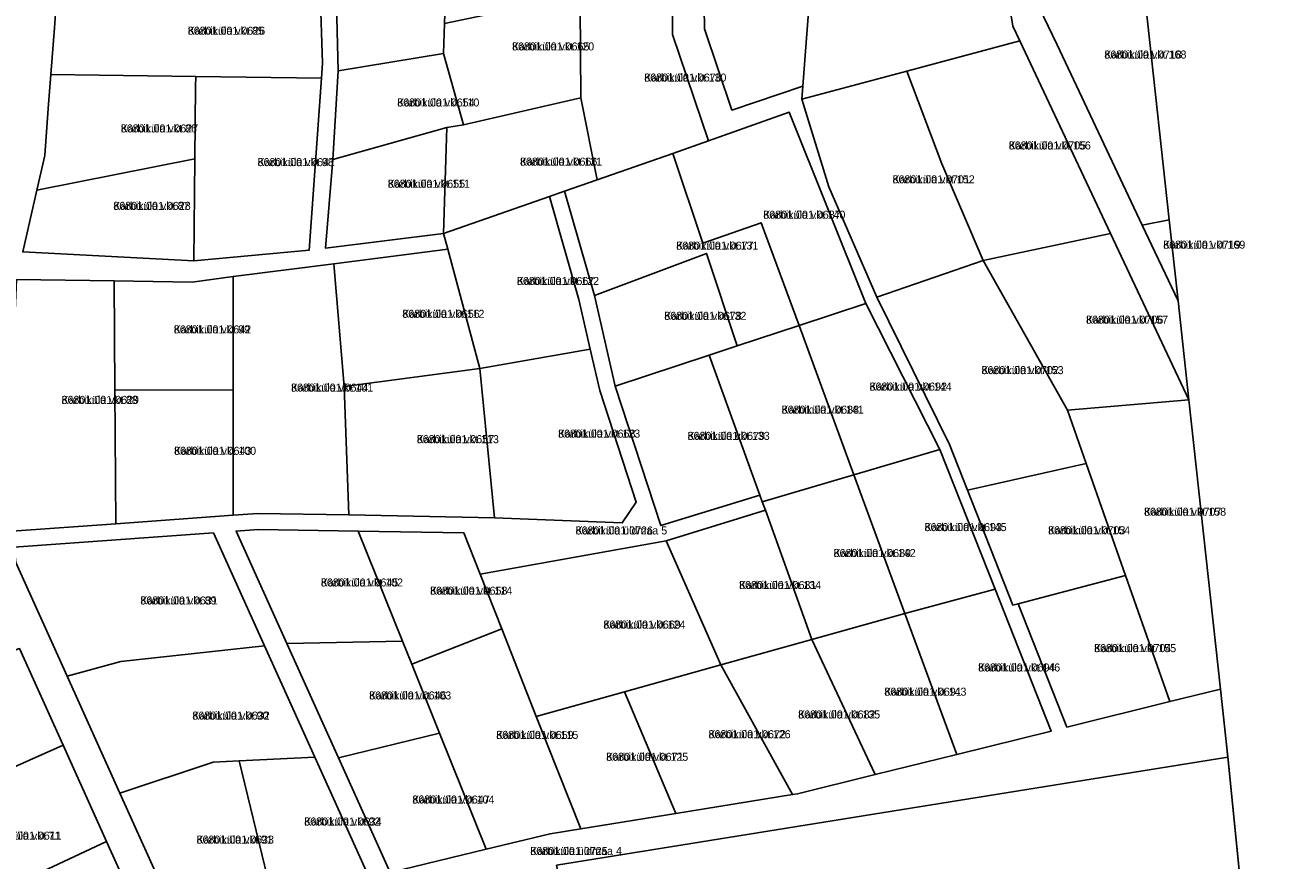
# Model space of a CAD drawing. Extents: x 484607 to 525396, y 6554521 to 6586559.
# Drawn here: x 517147.5 to 517380.7, y 6565288.3 to 6565444.8 of the extents above; entities that cross this region are included whole.
import ezdxf

# ---------------------------------------------------------------- set-up
doc = ezdxf.new("R2010")
doc.units = 0
for name, color, linetype in [('L_AADRESS', 7, 'Continuous'), ('PIIR', 7, 'Continuous'), ('TUNNUS', 7, 'Continuous')]:
    doc.layers.add(name, color=color, linetype=linetype)

msp = doc.modelspace()

# ---------------------------------------------------------------- linework, layer by layer
at = {"layer": 'PIIR'}
for points in [[(517389.61, 6565141.22), (517372.92, 6565307.66), (517371.53, 6565320.36), (517365.62, 6565374.54), (517363.6, 6565393.06), (517361.94, 6565408.22), (517357.88, 6565445.46), (517356.75, 6565455.84), (517355.62, 6565466.19), (517354.54, 6565476.06), (517353.45, 6565486.02), (517352, 6565499.3), (517350.78, 6565510.46), (517349.66, 6565520.75), (517348.53, 6565531.14), (517347.53, 6565540.29), (517346.37, 6565550.88), (517344.46, 6565568.44), (517344.15, 6565574.52), (517326.68, 6565708.93), (517381.83, 6565717.8)], [(517274.53, 6565464.55), (517274.86, 6565444.02), (517279.99, 6565428.81), (517293.29, 6565433.3), (517293.11, 6565430.86), (517298.16, 6565414.43), (517307.13, 6565393.74), (517320.76, 6565366.14), (517324.15, 6565357.6), (517332.65, 6565336.1), (517333.63, 6565336.35), (517342.77, 6565313.23), (517362.06, 6565318.01), (517371.53, 6565320.36), (517372.92, 6565307.64), (517247.1, 6565287.39)], [(517205.84, 6565451.13), (517206.19, 6565436.13), (517205.22, 6565419.54), (517203.82, 6565402.97), (517225.97, 6565405.68), (517226.76, 6565402.76), (517205.39, 6565400.01), (517186.54, 6565397.62), (517178.85, 6565396.59), (517164.22, 6565396.83), (517145.95, 6565397.1)], [(517153.32, 6565447.7), (517153.05, 6565444.2), (517152.38, 6565435.44), (517151.9, 6565429.1), (517151.24, 6565420.32), (517149.75, 6565413.79), (517147.12, 6565402.24), (517179.16, 6565400.54), (517200.79, 6565402.57), (517203.07, 6565434.8), (517203.27, 6565437.6), (517202.84, 6565451.04)], [(517338.41, 6565446.35), (517340.94, 6565441.01), (517356.89, 6565407.25), (517363.6, 6565393.06), (517365.62, 6565374.54), (517350.95, 6565405.67), (517333.93, 6565441.79), (517332.63, 6565444.55), (517331.62, 6565450.69)], [(517215.98, 6565286.02), (517233.94, 6565290.37), (517245.91, 6565293.28), (517251.66, 6565294.2), (517269.51, 6565297.07), (517291.35, 6565300.59), (517292.26, 6565300.74), (517306.86, 6565304.35), (517322.13, 6565308.13), (517339.83, 6565312.51), (517329.31, 6565339.05), (517318.98, 6565365.23), (517305.06, 6565392.61), (517290.7, 6565428.43), (517275.6, 6565423.05), (517268.87, 6565442.98), (517268.77, 6565450.06)], [(517145.13, 6565349.92), (517164.54, 6565351.33), (517186.51, 6565352.93), (517191.15, 6565353.26), (517208.24, 6565352.99), (517235.52, 6565352.42), (517259.44, 6565351.47), (517262.06, 6565355.37), (517255.23, 6565376.29), (517253.45, 6565384.04), (517251.32, 6565393.3), (517245.82, 6565412.6), (517248.65, 6565413.59), (517254.22, 6565394.05), (517258.13, 6565377.09), (517266.69, 6565350.97), (517285.24, 6565356.69), (517285.69, 6565355.43), (517286.26, 6565353.87), (517267.69, 6565348.14), (517232.82, 6565341.87), (517229.74, 6565349.65), (517209.99, 6565349.96), (517191.23, 6565350.26), (517187.1, 6565349.96), (517196.61, 6565328.9), (517206.27, 6565307.51), (517215.98, 6565286.02)], [(517212.02, 6565285.06), (517201.84, 6565307.61), (517192.42, 6565328.46), (517182.85, 6565349.65), (517145.48, 6565346.94)], [(517145.81, 6565344.07), (517155.44, 6565322.76), (517165.33, 6565300.84), (517176.36, 6565276.42)], [(517170.74, 6565274.29), (517162.82, 6565291.83), (517154.68, 6565309.84), (517146.51, 6565327.95)]]:
    msp.add_lwpolyline(points, dxfattribs=at)
for points in [[(517274.53, 6565464.55), (517295.86, 6565467.39), (517295.33, 6565460.32), (517293.29, 6565433.3), (517279.99, 6565428.81), (517274.86, 6565444.02)], [(517295.33, 6565460.32), (517331.7, 6565466.78), (517331.62, 6565450.69), (517332.63, 6565444.55), (517333.93, 6565441.79), (517312.77, 6565436.12), (517293.11, 6565430.86), (517293.29, 6565433.3)], [(517337.63, 6565452.48), (517356.75, 6565455.84), (517357.88, 6565445.46), (517361.94, 6565408.22), (517356.89, 6565407.25), (517340.94, 6565441.01), (517338.41, 6565446.35), (517337.62, 6565451.16)], [(517205.84, 6565451.13), (517226.44, 6565453.98), (517226.14, 6565445.02), (517225.96, 6565439.42), (517206.19, 6565436.13)], [(517226.14, 6565445.02), (517268.72, 6565453.92), (517268.77, 6565450.06), (517251.53, 6565448.2), (517251.66, 6565431.13), (517250.33, 6565430.79), (517229.73, 6565426.03), (517225.96, 6565439.42)], [(517153.05, 6565444.2), (517153.32, 6565447.7), (517179.69, 6565449.48), (517202.84, 6565451.04), (517203.27, 6565437.6), (517203.07, 6565434.8), (517179.53, 6565435.1), (517152.38, 6565435.44)], [(517251.53, 6565448.2), (517268.77, 6565450.06), (517268.87, 6565442.98), (517275.6, 6565423.05), (517268.94, 6565420.68), (517254.74, 6565415.72), (517251.66, 6565431.13)], [(517312.77, 6565436.12), (517333.93, 6565441.79), (517350.95, 6565405.67), (517327.07, 6565400.62), (517319.33, 6565418.73)], [(517206.19, 6565436.13), (517225.96, 6565439.42), (517229.73, 6565426.03), (517226.58, 6565425.55), (517205.22, 6565419.54)], [(517293.11, 6565430.86), (517312.77, 6565436.12), (517319.33, 6565418.73), (517327.07, 6565400.62), (517307.13, 6565393.74), (517298.16, 6565414.43)], [(517151.9, 6565429.1), (517152.38, 6565435.44), (517179.53, 6565435.1), (517179.51, 6565433.21), (517179.33, 6565419.7), (517149.75, 6565413.79), (517151.24, 6565420.32)], [(517179.53, 6565435.1), (517203.07, 6565434.8), (517200.79, 6565402.57), (517179.16, 6565400.54), (517179.33, 6565419.7), (517179.51, 6565433.21)], [(517226.58, 6565425.55), (517229.73, 6565426.03), (517250.33, 6565430.79), (517251.66, 6565431.13), (517254.74, 6565415.72), (517248.65, 6565413.59), (517245.82, 6565412.6), (517225.97, 6565405.68)], [(517268.94, 6565420.68), (517275.6, 6565423.05), (517290.7, 6565428.43), (517305.06, 6565392.61), (517292.58, 6565388.48), (517285.5, 6565407.71), (517274.56, 6565403.89)], [(517205.22, 6565419.54), (517226.58, 6565425.55), (517225.97, 6565405.68), (517203.82, 6565402.97)], [(517248.65, 6565413.59), (517254.74, 6565415.72), (517268.94, 6565420.68), (517274.56, 6565403.89), (517285.5, 6565407.71), (517292.58, 6565388.48), (517281.01, 6565384.66), (517275.21, 6565401.95), (517254.22, 6565394.05)], [(517149.75, 6565413.79), (517179.33, 6565419.7), (517179.16, 6565400.54), (517147.12, 6565402.24)], [(517225.97, 6565405.68), (517245.82, 6565412.6), (517251.32, 6565393.3), (517253.45, 6565384.04), (517232.77, 6565380.41), (517226.76, 6565402.76)], [(517356.89, 6565407.25), (517361.94, 6565408.22), (517363.6, 6565393.06)], [(517327.07, 6565400.62), (517350.95, 6565405.67), (517365.62, 6565374.54), (517342.88, 6565372.6)], [(517205.39, 6565400.01), (517226.76, 6565402.76), (517232.77, 6565380.41), (517207.33, 6565377.03)], [(517254.22, 6565394.05), (517275.21, 6565401.95), (517281.01, 6565384.66), (517275.76, 6565382.92), (517258.13, 6565377.09)], [(517186.54, 6565397.62), (517205.39, 6565400.01), (517207.33, 6565377.03), (517208.24, 6565352.99), (517191.15, 6565353.26), (517186.51, 6565352.93), (517186.53, 6565376.33)], [(517307.13, 6565393.74), (517327.07, 6565400.62), (517342.88, 6565372.6), (517346.39, 6565362.62), (517324.15, 6565357.6), (517320.76, 6565366.14)], [(517145.95, 6565397.1), (517164.22, 6565396.83), (517164.36, 6565376.38), (517164.54, 6565351.33), (517145.13, 6565349.92), (517144.23, 6565357.67)], [(517164.22, 6565396.83), (517178.85, 6565396.59), (517186.54, 6565397.62), (517186.53, 6565376.33), (517164.36, 6565376.38)], [(517292.58, 6565388.48), (517305.06, 6565392.61), (517318.98, 6565365.23), (517302.87, 6565360.49)], [(517275.76, 6565382.92), (517281.01, 6565384.66), (517292.58, 6565388.48), (517302.87, 6565360.49), (517285.69, 6565355.43), (517285.24, 6565356.69)], [(517232.77, 6565380.41), (517253.45, 6565384.04), (517255.23, 6565376.29), (517262.06, 6565355.37), (517259.44, 6565351.47), (517235.52, 6565352.42)], [(517258.13, 6565377.09), (517275.76, 6565382.92), (517285.24, 6565356.69), (517266.69, 6565350.97)], [(517207.33, 6565377.03), (517232.77, 6565380.41), (517235.52, 6565352.42), (517208.24, 6565352.99)], [(517164.36, 6565376.38), (517186.53, 6565376.33), (517186.51, 6565352.93), (517164.54, 6565351.33)], [(517342.88, 6565372.6), (517365.62, 6565374.54), (517371.53, 6565320.36), (517362.06, 6565318.01), (517353.77, 6565341.61), (517346.39, 6565362.62)], [(517302.87, 6565360.49), (517318.98, 6565365.23), (517329.31, 6565339.05), (517312.42, 6565334.54)], [(517324.15, 6565357.6), (517346.39, 6565362.62), (517353.77, 6565341.61), (517333.63, 6565336.35), (517332.65, 6565336.1)], [(517285.69, 6565355.43), (517302.87, 6565360.49), (517312.42, 6565334.54), (517294.98, 6565329.67), (517286.26, 6565353.87)], [(517267.69, 6565348.14), (517286.26, 6565353.87), (517294.98, 6565329.67), (517277.94, 6565324.91)], [(517187.1, 6565349.96), (517191.23, 6565350.26), (517209.99, 6565349.96), (517218.29, 6565329.32), (517196.61, 6565328.9)], [(517209.99, 6565349.96), (517229.74, 6565349.65), (517232.82, 6565341.87), (517236.87, 6565331.63), (517220.01, 6565325.02), (517218.29, 6565329.32)], [(517145.48, 6565346.94), (517182.85, 6565349.65), (517192.42, 6565328.46), (517165.51, 6565325.52), (517155.44, 6565322.76), (517145.81, 6565344.07)], [(517232.82, 6565341.87), (517267.69, 6565348.14), (517277.94, 6565324.91), (517259.87, 6565319.86), (517243.34, 6565315.25), (517236.87, 6565331.63)], [(517333.63, 6565336.35), (517353.77, 6565341.61), (517362.06, 6565318.01), (517342.77, 6565313.23)], [(517312.42, 6565334.54), (517329.31, 6565339.05), (517339.83, 6565312.51), (517322.13, 6565308.13)], [(517294.98, 6565329.67), (517312.42, 6565334.54), (517322.13, 6565308.13), (517306.86, 6565304.35)], [(517220.01, 6565325.02), (517236.87, 6565331.63), (517243.34, 6565315.25), (517251.66, 6565294.2), (517245.91, 6565293.28), (517233.94, 6565290.37), (517225.22, 6565312.08)], [(517196.61, 6565328.9), (517218.29, 6565329.32), (517220.01, 6565325.02), (517225.22, 6565312.08), (517206.27, 6565307.51)], [(517277.94, 6565324.91), (517294.98, 6565329.67), (517306.86, 6565304.35), (517292.26, 6565300.74), (517291.35, 6565300.59)], [(517106.7, 6565313.65), (517146.51, 6565327.95), (517154.68, 6565309.84), (517116.74, 6565292.98), (517114.44, 6565297.64), (517107.88, 6565311.13)], [(517155.44, 6565322.76), (517165.51, 6565325.52), (517192.42, 6565328.46), (517201.84, 6565307.61), (517187.67, 6565306.91), (517182.8, 6565306.65), (517165.33, 6565300.84)], [(517259.87, 6565319.86), (517277.94, 6565324.91), (517291.35, 6565300.59), (517269.51, 6565297.07)], [(517243.34, 6565315.25), (517259.87, 6565319.86), (517269.51, 6565297.07), (517251.66, 6565294.2)], [(517206.27, 6565307.51), (517225.22, 6565312.08), (517233.94, 6565290.37), (517215.98, 6565286.02)], [(517116.74, 6565292.98), (517154.68, 6565309.84), (517162.82, 6565291.83), (517125.83, 6565274.49)], [(517165.33, 6565300.84), (517182.8, 6565306.65), (517187.67, 6565306.91), (517194.02, 6565280.7), (517176.36, 6565276.42)], [(517187.67, 6565306.91), (517201.84, 6565307.61), (517212.02, 6565285.06), (517194.02, 6565280.7)], [(517247.1, 6565287.39), (517372.92, 6565307.64), (517389.61, 6565141.2), (517423.81, 6564799.48), (517424.42, 6564793.33), (517424.01, 6564793.33), (517421.1, 6564793.33), (517406.03, 6564790.74), (517391.56, 6564789.69), (517380.65, 6564790.4), (517374.55, 6564790.04), (517369.47, 6564788.41), (517361.44, 6564787.65), (517356.32, 6564787.99), (517348.91, 6564789.36), (517345, 6564788.57), (517343.63, 6564795.47)], [(517125.83, 6565274.49), (517162.82, 6565291.83), (517170.74, 6565274.29), (517141.07, 6565264.25), (517131.98, 6565262.06)]]:
    msp.add_lwpolyline(points, close=True, dxfattribs=at)

# ---------------------------------------------------------------- texts
at = {"layer": 'L_AADRESS'}
for s, p in [('Karbiküla vkt 85', (517178.03, 6565442.92)), ('Karbiküla vkt 120', (517238.79, 6565439.98)), ('Karbiküla vkt 168', (517349.78, 6565438.46)), ('Karbiküla vkt 130', (517263.57, 6565434.15)), ('Karbiküla vkt 110', (517217.28, 6565429.48)), ('Karbiküla vkt 86', (517165.48, 6565424.62)), ('Karbiküla vkt 156', (517331.86, 6565421.43)), ('Karbiküla vkt 98', (517191.11, 6565418.31)), ('Karbiküla vkt 121', (517240.28, 6565418.4)), ('Karbiküla vkt 111', (517215.5, 6565414.26)), ('Karbiküla vkt 152', (517310.09, 6565415.08)), ('Karbiküla vkt 87', (517164.08, 6565410.12)), ('Karbiküla vkt 140', (517285.87, 6565408.46)), ('Karbiküla vkt 131', (517269.56, 6565402.67)), ('Karbiküla vkt 169', (517360.81, 6565402.84)), ('Karbiküla vkt 122', (517239.71, 6565396.05)), ('Karbiküla vkt 112', (517218.23, 6565389.9)), ('Karbiküla vkt 132', (517267.32, 6565389.52)), ('Karbiküla vkt 157', (517346.34, 6565388.8)), ('Karbiküla vkt 99', (517175.41, 6565386.98)), ('Karbiküla vkt 153', (517326.76, 6565379.35)), ('Karbiküla vkt 144', (517305.78, 6565376.27)), ('Karbiküla vkt 101', (517197.38, 6565376.08)), ('Karbiküla vkt 88', (517154.38, 6565373.78)), ('Karbiküla vkt 141', (517289.31, 6565371.95)), ('Karbiküla vkt 123', (517247.42, 6565367.46)), ('Karbiküla vkt 133', (517271.69, 6565367.04)), ('Karbiküla vkt 113', (517220.94, 6565366.42)), ('Karbiküla vkt 100', (517175.45, 6565364.24)), ('Karbiküla vkt 158', (517357.21, 6565352.83)), ('Karbiküla üldmaa 5', (517250.7, 6565349.32)), ('Karbiküla vkt 145', (517316.09, 6565349.95)), ('Karbiküla vkt 154', (517339.23, 6565349.36)), ('Karbiküla vkt 142', (517299.05, 6565345.09)), ('Karbiküla vkt 102', (517202.98, 6565339.58)), ('Karbiküla vkt 134', (517281.33, 6565339.1)), ('Karbiküla vkt 114', (517223.43, 6565338.05)), ('Karbiküla vkt 89', (517169.14, 6565336.21)), ('Karbiküla vkt 124', (517255.9, 6565331.7)), ('Karbiküla vkt 155', (517347.85, 6565327.28)), ('Karbiküla vkt 146', (517326.12, 6565323.66)), ('Karbiküla vkt 103', (517212.01, 6565318.42)), ('Karbiküla vkt 143', (517308.55, 6565319.12)), ('Karbiküla vkt 90', (517178.88, 6565314.65)), ('Karbiküla vkt 135', (517292.4, 6565314.86)), ('Karbiküla vkt 115', (517235.83, 6565311.03)), ('Karbiküla vkt 126', (517275.61, 6565311.16)), ('Karbiküla vkt 125', (517256.43, 6565306.93)), ('Karbiküla vkt 104', (517220.11, 6565298.93)), ('Karbiküla vkt 92', (517199.85, 6565294.81)), ('Karbiküla vkt 71', (517139.9, 6565292.16)), ('Karbiküla vkt 91', (517179.68, 6565291.42)), ('Karbiküla üldmaa 4', (517242.21, 6565289.29))]:
    msp.add_text(s, height=1.5, dxfattribs=at).set_placement(p)
at = {"layer": 'TUNNUS'}
for s, p in [('86801:001:0626', (517178.03, 6565442.92)), ('86801:001:0665', (517238.79, 6565439.98)), ('86801:001:0718', (517349.78, 6565438.46)), ('86801:001:0676', (517263.57, 6565434.15)), ('86801:001:0654', (517217.28, 6565429.48)), ('86801:001:0627', (517165.48, 6565424.62)), ('86801:001:0705', (517331.86, 6565421.43)), ('86801:001:0641', (517191.11, 6565418.31)), ('86801:001:0666', (517240.28, 6565418.4)), ('86801:001:0655', (517215.5, 6565414.26)), ('86801:001:0701', (517310.09, 6565415.08)), ('86801:001:0628', (517164.08, 6565410.12)), ('86801:001:0687', (517285.87, 6565408.46)), ('86801:001:0677', (517269.56, 6565402.67)), ('86801:001:0719', (517360.81, 6565402.84)), ('86801:001:0667', (517239.71, 6565396.05)), ('86801:001:0656', (517218.23, 6565389.9)), ('86801:001:0678', (517267.32, 6565389.52)), ('86801:001:0706', (517346.34, 6565388.8)), ('86801:001:0642', (517175.41, 6565386.98)), ('86801:001:0702', (517326.76, 6565379.35)), ('86801:001:0644', (517197.38, 6565376.08)), ('86801:001:0692', (517305.78, 6565376.27)), ('86801:001:0629', (517154.38, 6565373.78)), ('86801:001:0688', (517289.31, 6565371.95)), ('86801:001:0668', (517247.42, 6565367.46)), ('86801:001:0679', (517271.69, 6565367.04)), ('86801:001:0657', (517220.94, 6565366.42)), ('86801:001:0643', (517175.45, 6565364.24)), ('86801:001:0707', (517357.21, 6565352.83)), ('86801:001:0726', (517250.7, 6565349.32)), ('86801:001:0693', (517316.09, 6565349.95)), ('86801:001:0703', (517339.23, 6565349.36)), ('86801:001:0689', (517299.05, 6565345.09)), ('86801:001:0645', (517202.98, 6565339.58)), ('86801:001:0681', (517281.33, 6565339.1)), ('86801:001:0658', (517223.43, 6565338.05)), ('86801:001:0631', (517169.14, 6565336.21)), ('86801:001:0669', (517255.9, 6565331.7)), ('86801:001:0704', (517347.85, 6565327.28)), ('86801:001:0694', (517326.12, 6565323.66)), ('86801:001:0646', (517212.01, 6565318.42)), ('86801:001:0691', (517308.55, 6565319.12)), ('86801:001:0632', (517178.88, 6565314.65)), ('86801:001:0682', (517292.4, 6565314.86)), ('86801:001:0659', (517235.83, 6565311.03)), ('86801:001:0672', (517275.61, 6565311.16)), ('86801:001:0671', (517256.43, 6565306.93)), ('86801:001:0647', (517220.11, 6565298.93)), ('86801:001:0634', (517199.85, 6565294.81)), ('86801:001:0611', (517139.9, 6565292.16)), ('86801:001:0633', (517179.68, 6565291.42)), ('86801:001:0725', (517242.21, 6565289.29))]:
    msp.add_text(s, height=1.5, dxfattribs=at).set_placement(p)

doc.saveas('drawing.dxf')
